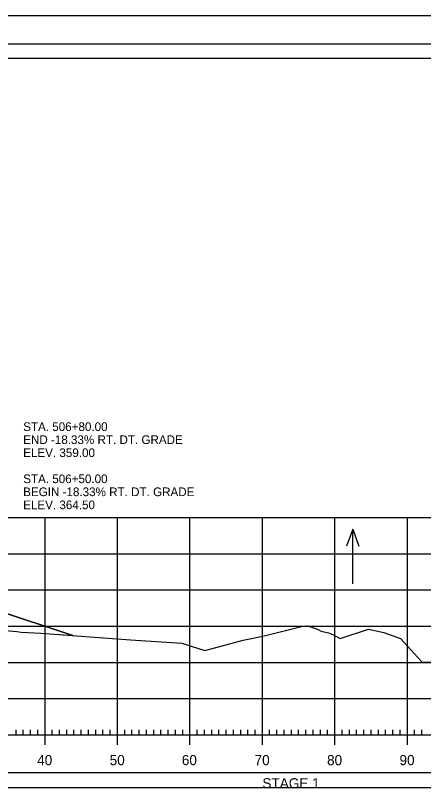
# Model space of a CAD drawing. Extents: x 1368910 to 1369601, y 380116 to 380950.
# Drawn here: x 1369116.2 to 1369172.5, y 380416.7 to 380523.8 of the extents above; entities that cross this region are included whole.
import ezdxf

# ---------------------------------------------------------------- set-up
doc = ezdxf.new("R2010")
doc.units = 0
for name, color, linetype in [('_STAGE 1 FILL', 7, 'Continuous'), ('Notes', 7, 'Continuous'), ('R_Axis', 7, 'Continuous'), ('R_Axis Annot', 7, 'Continuous'), ('R_Border', 7, 'Continuous'), ('R_Border Plan-Plan', 7, 'Continuous'), ('R_Exist Surface', 7, 'Continuous'), ('R_Fin Surface', 7, 'Continuous'), ('R_Grid', 7, 'Continuous'), ('R_No Plot', 7, 'Continuous'), ('R_Water Annot', 7, 'Continuous')]:
    doc.layers.add(name, color=color, linetype=linetype)

msp = doc.modelspace()

# ---------------------------------------------------------------- linework, layer by layer
at = {"layer": '_STAGE 1 FILL'}
for points in [[(1369102.85, 380443.15), (1369105.68, 380442.2), (1369109.44, 380440.52), (1369113.17, 380438.95), (1369116.36, 380438.67), (1369116.96, 380438.6), (1369119.66, 380438.44), (1369124.06, 380438.12)], [(1369124.06, 380438.12), (1369113.24, 380441.73), (1369107.04, 380442.76)]]:
    msp.add_lwpolyline(points, dxfattribs=at)
at = {"layer": 'R_Axis'}
for p, q in [((1369120.24, 380423.02), (1369120.24, 380425.82)), ((1369130.24, 380423.02), (1369130.24, 380425.82)), ((1369140.24, 380423.02), (1369140.24, 380425.82)), ((1369150.24, 380423.02), (1369150.24, 380425.82)), ((1369160.24, 380423.02), (1369160.24, 380425.82)), ((1369170.24, 380423.02), (1369170.24, 380425.82)), ((1369116.24, 380424.42), (1369116.24, 380425.12)), ((1369117.24, 380424.42), (1369117.24, 380425.12)), ((1369118.24, 380424.42), (1369118.24, 380425.12)), ((1369119.24, 380424.42), (1369119.24, 380425.12)), ((1369121.24, 380424.42), (1369121.24, 380425.12)), ((1369122.24, 380424.42), (1369122.24, 380425.12)), ((1369123.24, 380424.42), (1369123.24, 380425.12)), ((1369124.24, 380424.42), (1369124.24, 380425.12)), ((1369125.24, 380424.42), (1369125.24, 380425.12)), ((1369126.24, 380424.42), (1369126.24, 380425.12)), ((1369127.24, 380424.42), (1369127.24, 380425.12)), ((1369128.24, 380424.42), (1369128.24, 380425.12)), ((1369129.24, 380424.42), (1369129.24, 380425.12)), ((1369131.24, 380424.42), (1369131.24, 380425.12)), ((1369132.24, 380424.42), (1369132.24, 380425.12)), ((1369133.24, 380424.42), (1369133.24, 380425.12)), ((1369134.24, 380424.42), (1369134.24, 380425.12)), ((1369135.24, 380424.42), (1369135.24, 380425.12)), ((1369136.24, 380424.42), (1369136.24, 380425.12)), ((1369137.24, 380424.42), (1369137.24, 380425.12)), ((1369138.24, 380424.42), (1369138.24, 380425.12)), ((1369139.24, 380424.42), (1369139.24, 380425.12)), ((1369141.24, 380424.42), (1369141.24, 380425.12)), ((1369142.24, 380424.42), (1369142.24, 380425.12)), ((1369143.24, 380424.42), (1369143.24, 380425.12)), ((1369144.24, 380424.42), (1369144.24, 380425.12)), ((1369145.24, 380424.42), (1369145.24, 380425.12)), ((1369146.24, 380424.42), (1369146.24, 380425.12)), ((1369147.24, 380424.42), (1369147.24, 380425.12)), ((1369148.24, 380424.42), (1369148.24, 380425.12)), ((1369149.24, 380424.42), (1369149.24, 380425.12)), ((1369151.24, 380424.42), (1369151.24, 380425.12)), ((1369152.24, 380424.42), (1369152.24, 380425.12)), ((1369153.24, 380424.42), (1369153.24, 380425.12)), ((1369154.24, 380424.42), (1369154.24, 380425.12)), ((1369155.24, 380424.42), (1369155.24, 380425.12)), ((1369156.24, 380424.42), (1369156.24, 380425.12)), ((1369157.24, 380424.42), (1369157.24, 380425.12)), ((1369158.24, 380424.42), (1369158.24, 380425.12)), ((1369159.24, 380424.42), (1369159.24, 380425.12)), ((1369161.24, 380424.42), (1369161.24, 380425.12)), ((1369162.24, 380424.42), (1369162.24, 380425.12)), ((1369163.24, 380424.42), (1369163.24, 380425.12)), ((1369164.24, 380424.42), (1369164.24, 380425.12)), ((1369165.24, 380424.42), (1369165.24, 380425.12)), ((1369166.24, 380424.42), (1369166.24, 380425.12)), ((1369167.24, 380424.42), (1369167.24, 380425.12)), ((1369168.24, 380424.42), (1369168.24, 380425.12)), ((1369169.24, 380424.42), (1369169.24, 380425.12)), ((1369171.24, 380424.42), (1369171.24, 380425.12)), ((1369172.24, 380424.42), (1369172.24, 380425.12)), ((1368940.24, 380424.42), (1369220.24, 380424.42))]:
    msp.add_line(p, q, dxfattribs=at)
at = {"layer": 'R_Border'}
msp.add_line((1368922.24, 380519.88), (1369238.42, 380519.88), dxfattribs=at)
at = {"layer": 'R_Border Plan-Plan'}
msp.add_line((1368922.24, 380417.15), (1369238.42, 380417.15), dxfattribs=at)
at = {"layer": 'R_Exist Surface'}
msp.add_lwpolyline([(1369113.17, 380438.95), (1369116.36, 380438.67), (1369116.96, 380438.6), (1369119.66, 380438.44), (1369132.04, 380437.55), (1369139.13, 380437.09), (1369139.4, 380436.99), (1369142.31, 380436.08), (1369147.59, 380437.51), (1369150.31, 380438.02), (1369155.64, 380439.39), (1369156.48, 380439.48), (1369157.29, 380439.17), (1369157.92, 380438.97), (1369158.36, 380438.74), (1369159.34, 380438.5), (1369160.05, 380438.23), (1369160.98, 380437.74), (1369164.86, 380439.02), (1369166.98, 380438.56), (1369169.29, 380437.71), (1369172.14, 380434.59), (1369172.3, 380434.44), (1369173.56, 380434.51)], dxfattribs=at)
at = {"layer": 'R_Fin Surface'}
msp.add_lwpolyline([(1369037.72, 380439.99), (1369039.87, 380439.27), (1369047.24, 380441.73), (1369055.52, 380443.11), (1369061.24, 380444.06), (1369069.24, 380444.38), (1369080.24, 380444.6), (1369091.24, 380444.38), (1369099.24, 380444.06), (1369104.97, 380443.11), (1369113.24, 380441.73), (1369124.06, 380438.12)], dxfattribs=at)
at = {"layer": 'R_Grid'}
for p, q in [((1368940.24, 380454.42), (1369220.24, 380454.42)), ((1369120.24, 380424.42), (1369120.24, 380454.42)), ((1369130.24, 380424.42), (1369130.24, 380454.42)), ((1369140.24, 380424.42), (1369140.24, 380454.42)), ((1369150.24, 380424.42), (1369150.24, 380454.42)), ((1369160.24, 380424.42), (1369160.24, 380454.42)), ((1369170.24, 380424.42), (1369170.24, 380454.42)), ((1368940.24, 380449.42), (1369220.24, 380449.42)), ((1368940.24, 380444.42), (1369220.24, 380444.42)), ((1368940.24, 380439.42), (1369220.24, 380439.42)), ((1368940.24, 380434.42), (1369220.24, 380434.42)), ((1368940.24, 380429.42), (1369220.24, 380429.42)), ((1368940.24, 380424.42), (1369220.24, 380424.42))]:
    msp.add_line(p, q, dxfattribs=at)
at = {"layer": 'R_No Plot'}
for points in [[(1368909.84, 380523.78), (1369243.18, 380523.78), (1369243.18, 380310.44), (1368909.84, 380310.44)], [(1369236.42, 380419.15), (1368924.24, 380419.15), (1368924.24, 380517.88), (1369173.78, 380517.88), (1369173.78, 380508), (1369191.32, 380508), (1369215.42, 380508), (1369215.42, 380485.67), (1369236.42, 380485.67)], [(1368924.24, 380517.88), (1369173.78, 380517.88), (1369173.78, 380508), (1369191.32, 380508), (1369215.42, 380508), (1369215.42, 380485.67), (1369236.42, 380485.67), (1369236.42, 380316.42), (1368924.24, 380316.42)]]:
    msp.add_lwpolyline(points, close=True, dxfattribs=at)
at = {"layer": 'R_Water Annot'}
for p, q in [((1369162.7, 380452.8), (1369161.86, 380450.49)), ((1369162.7, 380445.26), (1369162.7, 380452.8)), ((1369162.7, 380452.8), (1369163.54, 380450.49))]:
    msp.add_line(p, q, dxfattribs=at)

# ---------------------------------------------------------------- texts
at = {"layer": 'Notes'}
for s, p in [('STA. 506+80.00', (1369117.23, 380466.38)), ('END -18.33% RT. DT. GRADE', (1369117.23, 380464.58)), ('ELEV. 359.00', (1369117.23, 380462.78)), ('STA. 506+50.00', (1369117.23, 380459.18)), ('BEGIN -18.33% RT. DT. GRADE', (1369117.23, 380457.38)), ('ELEV. 364.50', (1369117.23, 380455.58))]:
    msp.add_text(s, height=1.2, dxfattribs=at).set_placement(p)
at = {"layer": 'R_Axis Annot'}
for s, p in [('40', (1369119.16, 380420.22)), ('50', (1369129.16, 380420.22)), ('60', (1369139.12, 380420.22)), ('70', (1369149.16, 380420.22)), ('80', (1369159.16, 380420.22)), ('90', (1369169.16, 380420.22)), ('STAGE 1', (1369150.24, 380417.02))]:
    msp.add_text(s, height=1.4, dxfattribs=at).set_placement(p)

doc.saveas('drawing.dxf')
